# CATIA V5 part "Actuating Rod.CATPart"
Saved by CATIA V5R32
Part number: Actuating Rod
Bounding box of the stored display mesh (mm): x -17.5 to 17.5, y -11.818 to 195.322, z -21 to 21
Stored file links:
  D:\PROJECTS\Project 2022\CATIA V5 6R 2022\Resources\Part Files\c13_catia_v5_6r2022_prt\c13_catia_v5-6r2022_figr_13-41\Part & Asm files\Actuating Rod.CATPart
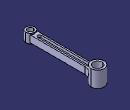
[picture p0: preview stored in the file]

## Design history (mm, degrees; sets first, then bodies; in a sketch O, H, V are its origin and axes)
Body1 (main body)
  Sketch1 on xy-plane, origin (0, 0, 0), H (1, 0, 0), V (0, 1, 0)
    arc A1 centre (0, 0) radius 12 from (-9, 7.9373) to (9, 7.9373) ccw
    arc A2 centre (0, 178) radius 17.5 from (13.5991, 166.9857) to (-13.5991, 166.9857) ccw
    point P1 (0, 178)
    line L1 (9, 154) -> (9, 7.9373)
    point P2 (9, 154)
    point P3 (9, 7.9373)
    arc A3 centre (29.6324, 154) radius 20.6324 from (9, 154) to (13.5991, 166.9857) cw
    point P5 (13.5991, 166.9857)
    point P6 (-13.5991, 166.9857)
    point P7 (-9, 154)
    arc A4 centre (-29.6324, 154) radius 20.6324 from (-9, 154) to (-13.5991, 166.9857) ccw
    point P9 (-9, 7.9373)
    line L2 (-9, 154) -> (-9, 7.9373)
    radius A2 = 17.5
    radius A1 = 12
    distance O P1 = 178
    distance V L1 = 9
    distance P1 P2 V = 24
    coincidence: P1 V
    vertical: L1 V
    tangency: A3 L1, A3 A2
    symmetry: P5 P6 V, P2 P7 V, A3 A4 V, P3 P9 V, L1 L2 V
  Pad1: profile Sketch1, direction (0, 0, 1), length 9, mirrored extent
  Sketch2 on xy-plane, origin (0, 0, 0), H (1, 0, 0), V (0, 1, 0)
    circle A1 centre (0, 0) radius 12
    reference projected arc E1 centre (0, 0) radius 12 from (-9, 7.9373) to (9, 7.9373) ccw from edge of Pad1
    reference projected arc E2 centre (0, 0) radius 12 from (-9, 7.9373) to (9, 7.9373) ccw from edge of Pad1
    reference projected arc E3 centre (0, 0) radius 12 from (-9, 7.9373) to (9, 7.9373) ccw from edge of Pad1
    concentricity: A1 E1, A1 E2
    tangency: A1 E3
  Pad2: profile Sketch2, direction (0, 0, 1), length 12, mirrored extent
  Sketch3 on xy-plane, origin (0, 0, 0), H (1, 0, 0), V (0, 1, 0)
    circle A1 centre (0, 178) radius 17.5
    point P1 (0, 178)
    reference projected arc E1 centre (0, 178) radius 17.5 from (13.5991, 166.9857) to (-13.5991, 166.9857) ccw from edge of Pad1
    reference projected arc E2 centre (0, 178) radius 17.5 from (13.5991, 166.9857) to (-13.5991, 166.9857) ccw from edge of Pad1
    coincidence: P1 V
    concentricity: A1 E1
    tangency: E2 A1
  Pad3: profile Sketch3, direction (0, 0, 1), length 21, mirrored extent
  Sketch4 on xy-plane, origin (0, 0, 0), H (1, 0, 0), V (0, 1, 0)
    circle A1 centre (0, 178) radius 12
    point P1 (0, 178)
    circle A2 centre (0, 0) radius 7.5
    reference projected circle E1 centre (0, 178) radius 17.5 from edge of Pad3
    radius A1 = 12
    radius A2 = 7.5
    coincidence: P1 V
    concentricity: A1 E1
  Pocket1: profile Sketch4, direction (0, 0, -1), length 21, mirrored extent
  Sketch5 on xy-plane, origin (0, 0, 0), H (1, 0, 0), V (0, 1, 0)
    construction line L1 (0, 24) -> (0, 154)
    point P1 (0, 24)
    line L2 (-5, 24) -> (-5, 154)
    line L3 (5, 154) -> (5, 24)
    arc A1 centre (0, 154) radius 5 from (-5, 154) to (5, 154) cw
    arc A2 centre (0, 24) radius 5 from (5, 24) to (-5, 24) cw
    length L1 = 130
    distance H P1 = 24
    radius A1 = 5
    coincidence: P1 V
    vertical: L1 V
    tangency: A1 L2, A2 L2, A1 L3, A2 L3
    parallelism: L1 L2
  Pocket2: profile Sketch5, direction (0, 0, -1), through (limit type 6), opposite side length -2.5
  Mirror1: of Pocket2, Sketch5, about xy-plane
